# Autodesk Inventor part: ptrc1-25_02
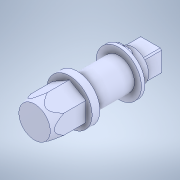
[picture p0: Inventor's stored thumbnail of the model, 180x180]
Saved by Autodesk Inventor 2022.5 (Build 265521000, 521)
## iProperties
Created: 2023-04
Part Number: ptrc1-25_02
Material: Generic
Document SubType Name: Modeling
Designer: ImaoCorp
Density: 1 g/cm^3
Appearance: Default
Author: ImaoCorp
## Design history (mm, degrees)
feature "ptrc1-25_02"
node "ソリッド1"
